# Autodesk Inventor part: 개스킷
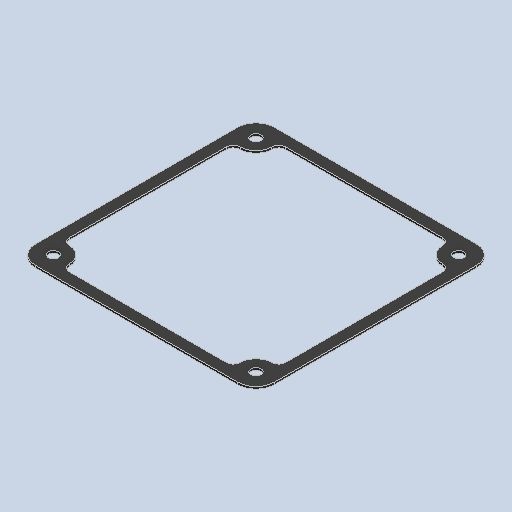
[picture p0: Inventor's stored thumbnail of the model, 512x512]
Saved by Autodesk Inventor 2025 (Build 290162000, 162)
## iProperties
Created: 2024-08
Part Number: 개스킷
Material: 고무
Document SubType Name: Modeling
Designer: rese9
Density: 0.93 g/cm^3
Appearance: 기본값
Author: jhkim
Sending System: Autodesk Inventor 2025
Preprocessor: ST-DEVELOPER v20
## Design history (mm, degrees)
feature "솔리드1"
node "솔리드2"
